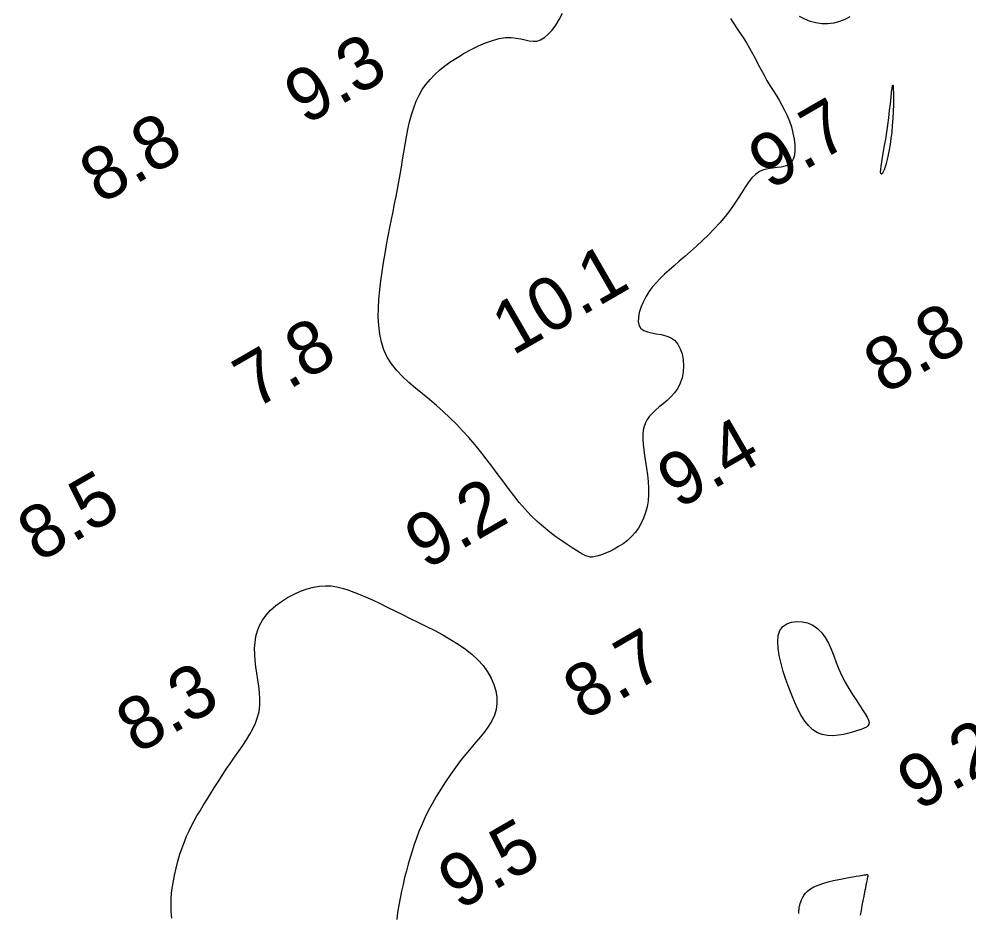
# Model space of a CAD drawing. Extents: x 3024098 to 3056816, y 418252 to 509144.
# Drawn here: x 3036813.5 to 3036902.9, y 419561.2 to 419645.5 of the extents above; entities that cross this region are included whole.
import ezdxf

# ---------------------------------------------------------------- set-up
doc = ezdxf.new("R2010")
doc.units = 0
doc.layers.add('V-CHAN-CONT-EL10', color=7, linetype='Continuous')
doc.layers.add('V-TOPO-SOUN-0911', color=7, linetype='Continuous')

msp = doc.modelspace()

# ---------------------------------------------------------------- linework, layer by layer
at = {"layer": 'V-CHAN-CONT-EL10'}
for points in [[(3036880.487, 419645.519), (3036880.767, 419645.077), (3036881.07, 419644.633), (3036881.384, 419644.181), (3036881.695, 419643.716), (3036881.996, 419643.232), (3036882.285, 419642.734), (3036882.566, 419642.225), (3036882.841, 419641.71), (3036883.113, 419641.194), (3036883.384, 419640.682), (3036883.658, 419640.178), (3036883.936, 419639.686), (3036884.22, 419639.21), (3036884.507, 419638.745), (3036884.793, 419638.286), (3036885.073, 419637.825), (3036885.343, 419637.357), (3036885.598, 419636.876), (3036885.835, 419636.376), (3036886.048, 419635.851), (3036886.234, 419635.298), (3036886.386, 419634.731), (3036886.497, 419634.165), (3036886.562, 419633.618), (3036886.575, 419633.107), (3036886.529, 419632.647), (3036886.417, 419632.255), (3036886.235, 419631.949), (3036885.978, 419631.738), (3036885.658, 419631.604), (3036885.289, 419631.524), (3036884.887, 419631.474), (3036884.464, 419631.429), (3036884.036, 419631.366), (3036883.616, 419631.261), (3036883.22, 419631.089), (3036882.858, 419630.833), (3036882.522, 419630.498), (3036882.202, 419630.094), (3036881.887, 419629.633), (3036881.565, 419629.126), (3036881.226, 419628.584), (3036880.858, 419628.017), (3036880.451, 419627.437), (3036879.996, 419626.854), (3036879.5, 419626.274), (3036878.972, 419625.7), (3036878.422, 419625.137), (3036877.86, 419624.589), (3036877.295, 419624.062), (3036876.736, 419623.559), (3036876.193, 419623.084), (3036875.674, 419622.641), (3036875.182, 419622.223), (3036874.716, 419621.821), (3036874.278, 419621.427), (3036873.867, 419621.033), (3036873.485, 419620.63), (3036873.131, 419620.211), (3036872.807, 419619.766), (3036872.515, 419619.291), (3036872.261, 419618.798), (3036872.055, 419618.302), (3036871.906, 419617.818), (3036871.823, 419617.362), (3036871.814, 419616.95), (3036871.889, 419616.596), (3036872.057, 419616.316), (3036872.321, 419616.119), (3036872.665, 419615.987), (3036873.068, 419615.895), (3036873.508, 419615.82), (3036873.964, 419615.737), (3036874.416, 419615.622), (3036874.84, 419615.45), (3036875.217, 419615.198), (3036875.528, 419614.847), (3036875.77, 419614.412), (3036875.943, 419613.912), (3036876.046, 419613.367), (3036876.08, 419612.798), (3036876.044, 419612.226), (3036875.939, 419611.669), (3036875.764, 419611.149), (3036875.522, 419610.682), (3036875.226, 419610.263), (3036874.889, 419609.885), (3036874.528, 419609.541), (3036874.157, 419609.223), (3036873.792, 419608.923), (3036873.447, 419608.632), (3036873.138, 419608.344), (3036872.876, 419608.05), (3036872.662, 419607.746), (3036872.494, 419607.427), (3036872.37, 419607.086), (3036872.286, 419606.719), (3036872.242, 419606.322), (3036872.235, 419605.888), (3036872.261, 419605.414), (3036872.319, 419604.895), (3036872.399, 419604.338), (3036872.49, 419603.752), (3036872.584, 419603.144), (3036872.669, 419602.524), (3036872.736, 419601.899), (3036872.775, 419601.277), (3036872.775, 419600.668), (3036872.729, 419600.079), (3036872.636, 419599.511), (3036872.497, 419598.969), (3036872.314, 419598.453), (3036872.089, 419597.967), (3036871.822, 419597.511), (3036871.515, 419597.089), (3036871.169, 419596.702), (3036870.789, 419596.351), (3036870.382, 419596.038), (3036869.961, 419595.761), (3036869.536, 419595.519), (3036869.12, 419595.313), (3036868.722, 419595.14), (3036868.355, 419595.001), (3036868.029, 419594.896), (3036867.752, 419594.823), (3036867.512, 419594.784), (3036867.294, 419594.782), (3036867.082, 419594.819), (3036866.861, 419594.896), (3036866.615, 419595.015), (3036866.328, 419595.179), (3036865.986, 419595.389), (3036865.577, 419595.647), (3036865.108, 419595.953), (3036864.592, 419596.304), (3036864.039, 419596.7), (3036863.462, 419597.139), (3036862.872, 419597.62), (3036862.28, 419598.142), (3036861.7, 419598.703), (3036861.139, 419599.302), (3036860.597, 419599.932), (3036860.068, 419600.588), (3036859.549, 419601.264), (3036859.035, 419601.952), (3036858.522, 419602.648), (3036858.006, 419603.344), (3036857.481, 419604.036), (3036856.946, 419604.716), (3036856.398, 419605.383), (3036855.836, 419606.037), (3036855.259, 419606.677), (3036854.668, 419607.3), (3036854.06, 419607.907), (3036853.436, 419608.496), (3036852.794, 419609.067), (3036852.136, 419609.619), (3036851.474, 419610.16), (3036850.82, 419610.698), (3036850.189, 419611.24), (3036849.594, 419611.795), (3036849.049, 419612.371), (3036848.567, 419612.976), (3036848.162, 419613.619), (3036847.845, 419614.305), (3036847.609, 419615.031), (3036847.448, 419615.792), (3036847.351, 419616.583), (3036847.311, 419617.398), (3036847.318, 419618.233), (3036847.365, 419619.082), (3036847.443, 419619.94), (3036847.544, 419620.802), (3036847.664, 419621.664), (3036847.798, 419622.521), (3036847.944, 419623.369), (3036848.097, 419624.204), (3036848.254, 419625.023), (3036848.411, 419625.82), (3036848.565, 419626.592), (3036848.712, 419627.336), (3036848.852, 419628.056), (3036848.987, 419628.758), (3036849.117, 419629.448), (3036849.242, 419630.132), (3036849.364, 419630.815), (3036849.484, 419631.503), (3036849.601, 419632.201), (3036849.718, 419632.914), (3036849.839, 419633.636), (3036849.967, 419634.359), (3036850.108, 419635.075), (3036850.265, 419635.777), (3036850.444, 419636.456), (3036850.648, 419637.106), (3036850.883, 419637.718), (3036851.152, 419638.288), (3036851.458, 419638.817), (3036851.802, 419639.312), (3036852.186, 419639.778), (3036852.611, 419640.22), (3036853.081, 419640.644), (3036853.596, 419641.055), (3036854.158, 419641.459), (3036854.766, 419641.857), (3036855.411, 419642.243), (3036856.078, 419642.607), (3036856.754, 419642.937), (3036857.426, 419643.222), (3036858.082, 419643.454), (3036858.707, 419643.621), (3036859.289, 419643.713), (3036859.817, 419643.725), (3036860.297, 419643.676), (3036860.737, 419643.591), (3036861.143, 419643.496), (3036861.525, 419643.414), (3036861.89, 419643.37), (3036862.246, 419643.39), (3036862.602, 419643.498), (3036862.962, 419643.713), (3036863.324, 419644.028), (3036863.681, 419644.428), (3036864.027, 419644.903), (3036864.358, 419645.437), (3036864.666, 419646.017)], [(3036891.732, 419645.684), (3036891.279, 419645.425), (3036890.776, 419645.226), (3036890.237, 419645.091), (3036889.677, 419645.023), (3036889.111, 419645.023), (3036888.554, 419645.095), (3036888.018, 419645.238), (3036887.503, 419645.449), (3036887.008, 419645.719)], [(3036827.861, 419560.761), (3036827.8, 419561.384), (3036827.78, 419562.03), (3036827.804, 419562.701), (3036827.869, 419563.39), (3036827.969, 419564.088), (3036828.1, 419564.786), (3036828.256, 419565.474), (3036828.433, 419566.143), (3036828.625, 419566.785), (3036828.827, 419567.391), (3036829.035, 419567.953), (3036829.251, 419568.478), (3036829.476, 419568.976), (3036829.712, 419569.457), (3036829.962, 419569.928), (3036830.228, 419570.4), (3036830.513, 419570.883), (3036830.817, 419571.384), (3036831.142, 419571.912), (3036831.487, 419572.462), (3036831.848, 419573.03), (3036832.221, 419573.609), (3036832.603, 419574.194), (3036832.992, 419574.78), (3036833.383, 419575.359), (3036833.774, 419575.928), (3036834.16, 419576.481), (3036834.535, 419577.021), (3036834.889, 419577.553), (3036835.215, 419578.081), (3036835.505, 419578.61), (3036835.751, 419579.144), (3036835.944, 419579.687), (3036836.076, 419580.244), (3036836.142, 419580.818), (3036836.152, 419581.406), (3036836.118, 419582.005), (3036836.051, 419582.61), (3036835.965, 419583.219), (3036835.872, 419583.827), (3036835.783, 419584.431), (3036835.711, 419585.027), (3036835.669, 419585.612), (3036835.662, 419586.184), (3036835.697, 419586.743), (3036835.781, 419587.287), (3036835.921, 419587.816), (3036836.122, 419588.33), (3036836.392, 419588.826), (3036836.736, 419589.305), (3036837.158, 419589.765), (3036837.647, 419590.2), (3036838.189, 419590.605), (3036838.77, 419590.973), (3036839.377, 419591.298), (3036839.995, 419591.574), (3036840.61, 419591.795), (3036841.209, 419591.955), (3036841.781, 419592.049), (3036842.331, 419592.081), (3036842.865, 419592.056), (3036843.392, 419591.979), (3036843.92, 419591.855), (3036844.455, 419591.689), (3036845.006, 419591.486), (3036845.58, 419591.251), (3036846.184, 419590.989), (3036846.817, 419590.704), (3036847.476, 419590.396), (3036848.159, 419590.07), (3036848.864, 419589.727), (3036849.588, 419589.371), (3036850.33, 419589.003), (3036851.087, 419588.626), (3036851.855, 419588.243), (3036852.625, 419587.849), (3036853.387, 419587.443), (3036854.129, 419587.021), (3036854.842, 419586.579), (3036855.514, 419586.114), (3036856.136, 419585.623), (3036856.696, 419585.102), (3036857.185, 419584.551), (3036857.599, 419583.974), (3036857.938, 419583.379), (3036858.198, 419582.775), (3036858.377, 419582.169), (3036858.474, 419581.568), (3036858.487, 419580.982), (3036858.413, 419580.417), (3036858.252, 419579.878), (3036858.013, 419579.36), (3036857.708, 419578.854), (3036857.345, 419578.352), (3036856.937, 419577.845), (3036856.495, 419577.324), (3036856.027, 419576.782), (3036855.547, 419576.21), (3036855.063, 419575.601), (3036854.581, 419574.96), (3036854.106, 419574.295), (3036853.644, 419573.614), (3036853.2, 419572.922), (3036852.778, 419572.228), (3036852.383, 419571.539), (3036852.021, 419570.862), (3036851.696, 419570.203), (3036851.404, 419569.56), (3036851.141, 419568.93), (3036850.904, 419568.308), (3036850.688, 419567.692), (3036850.49, 419567.079), (3036850.305, 419566.464), (3036850.129, 419565.844), (3036849.959, 419565.217), (3036849.796, 419564.582), (3036849.641, 419563.94), (3036849.497, 419563.29), (3036849.363, 419562.634), (3036849.243, 419561.972), (3036849.137, 419561.303), (3036849.048, 419560.629)], [(3036886.93, 419561.208), (3036886.936, 419561.322), (3036886.942, 419561.422), (3036886.949, 419561.512), (3036886.957, 419561.598), (3036886.969, 419561.684), (3036886.986, 419561.776), (3036887.008, 419561.879), (3036887.037, 419561.997), (3036887.074, 419562.136), (3036887.121, 419562.3), (3036887.186, 419562.484), (3036887.276, 419562.682), (3036887.398, 419562.89), (3036887.56, 419563.102), (3036887.771, 419563.313), (3036888.037, 419563.516), (3036888.367, 419563.707), (3036888.764, 419563.881), (3036889.214, 419564.038), (3036889.699, 419564.178), (3036890.202, 419564.302), (3036890.704, 419564.411), (3036891.188, 419564.506), (3036891.636, 419564.587), (3036892.03, 419564.655), (3036892.356, 419564.71), (3036892.617, 419564.755), (3036892.823, 419564.79), (3036892.98, 419564.816), (3036893.098, 419564.835), (3036893.183, 419564.848), (3036893.245, 419564.855), (3036893.291, 419564.86), (3036893.327, 419564.861), (3036893.357, 419564.861), (3036893.38, 419564.858), (3036893.397, 419564.853), (3036893.411, 419564.847), (3036893.42, 419564.839), (3036893.427, 419564.829), (3036893.432, 419564.819), (3036893.435, 419564.807), (3036893.437, 419564.793), (3036893.438, 419564.778), (3036893.438, 419564.76), (3036893.436, 419564.739), (3036893.434, 419564.714), (3036893.43, 419564.686), (3036893.424, 419564.654), (3036893.417, 419564.615), (3036893.408, 419564.564), (3036893.393, 419564.493), (3036893.374, 419564.394), (3036893.347, 419564.261), (3036893.311, 419564.085), (3036893.265, 419563.858), (3036893.207, 419563.574), (3036893.138, 419563.229), (3036893.059, 419562.833), (3036892.974, 419562.402), (3036892.887, 419561.95), (3036892.802, 419561.494), (3036892.723, 419561.047)]]:
    msp.add_lwpolyline(points, dxfattribs=at)
for points in [[(3036895.418, 419636.161), (3036895.497, 419636.839), (3036895.567, 419637.482), (3036895.628, 419638.065), (3036895.68, 419638.561), (3036895.726, 419638.944), (3036895.764, 419639.189), (3036895.795, 419639.269), (3036895.821, 419639.168), (3036895.839, 419638.903), (3036895.85, 419638.504), (3036895.852, 419637.997), (3036895.844, 419637.41), (3036895.824, 419636.772), (3036895.793, 419636.109), (3036895.749, 419635.449), (3036895.692, 419634.817), (3036895.622, 419634.219), (3036895.543, 419633.659), (3036895.456, 419633.14), (3036895.363, 419632.664), (3036895.267, 419632.237), (3036895.169, 419631.859), (3036895.072, 419631.536), (3036894.977, 419631.27), (3036894.888, 419631.064), (3036894.809, 419630.923), (3036894.741, 419630.849), (3036894.688, 419630.846), (3036894.654, 419630.917), (3036894.641, 419631.067), (3036894.652, 419631.297), (3036894.69, 419631.611), (3036894.751, 419632.001), (3036894.83, 419632.459), (3036894.922, 419632.977), (3036895.023, 419633.546), (3036895.128, 419634.157), (3036895.231, 419634.803), (3036895.33, 419635.475)], [(3036885.729, 419583.249), (3036885.478, 419584.01), (3036885.26, 419584.763), (3036885.089, 419585.494), (3036884.98, 419586.184), (3036884.946, 419586.819), (3036885.003, 419587.381), (3036885.164, 419587.853), (3036885.438, 419588.223), (3036885.807, 419588.49), (3036886.248, 419588.655), (3036886.738, 419588.722), (3036887.253, 419588.692), (3036887.769, 419588.567), (3036888.264, 419588.351), (3036888.713, 419588.046), (3036889.099, 419587.654), (3036889.43, 419587.189), (3036889.719, 419586.663), (3036889.979, 419586.09), (3036890.223, 419585.483), (3036890.465, 419584.855), (3036890.718, 419584.22), (3036890.995, 419583.591), (3036891.305, 419582.98), (3036891.64, 419582.393), (3036891.984, 419581.837), (3036892.326, 419581.315), (3036892.65, 419580.834), (3036892.943, 419580.399), (3036893.192, 419580.014), (3036893.383, 419579.685), (3036893.505, 419579.415), (3036893.557, 419579.197), (3036893.539, 419579.021), (3036893.455, 419578.877), (3036893.305, 419578.756), (3036893.091, 419578.648), (3036892.814, 419578.542), (3036892.477, 419578.431), (3036892.081, 419578.307), (3036891.639, 419578.182), (3036891.161, 419578.07), (3036890.662, 419577.986), (3036890.152, 419577.946), (3036889.645, 419577.963), (3036889.153, 419578.053), (3036888.688, 419578.23), (3036888.26, 419578.505), (3036887.867, 419578.873), (3036887.504, 419579.325), (3036887.168, 419579.85), (3036886.854, 419580.44), (3036886.557, 419581.084), (3036886.273, 419581.773), (3036885.997, 419582.499)]]:
    msp.add_lwpolyline(points, close=True, dxfattribs=at)

# ---------------------------------------------------------------- texts
at = {"layer": 'V-TOPO-SOUN-0911'}
for s, p in [('9.3', (3036840.427, 419635.411)), ('9.7', (3036884.167, 419629.281)), ('8.8', (3036821.137, 419627.961)), ('10.1 ', (3036859.968, 419613.703)), ('8.8', (3036895.027, 419610.051)), ('7.8', (3036835.637, 419608.641)), ('9.4', (3036875.567, 419599.221)), ('8.5', (3036815.291, 419594.208)), ('9.2', (3036851.777, 419593.521)), ('8.7', (3036866.707, 419579.311)), ('8.3', (3036824.587, 419576.161)), ('9.2', (3036898.177, 419570.781)), ('9.5', (3036854.921, 419561.428))]:
    msp.add_text(s, height=5, rotation=30, dxfattribs=at).set_placement(p)

doc.saveas('drawing.dxf')
